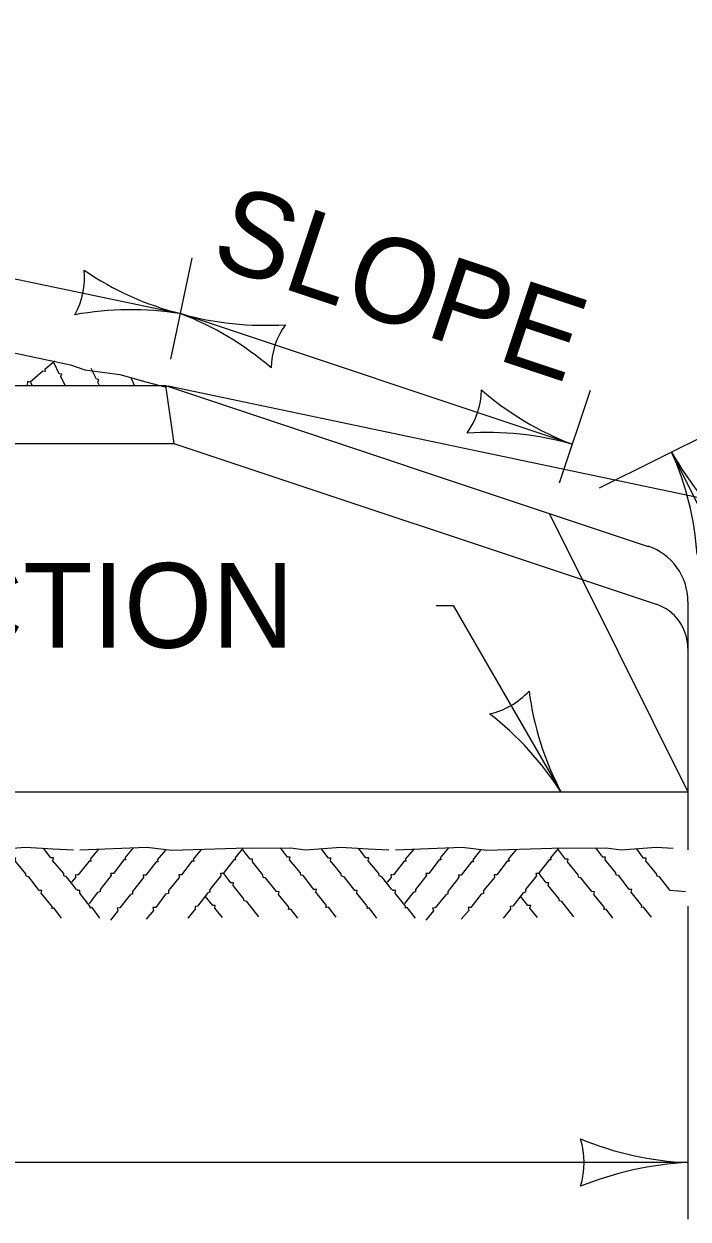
# Model space of a CAD drawing. Extents: x 49991.4 to 50022.1, y 49985 to 50011.4.
# Drawn here: x 50014.7 to 50015.17, y 49996.952 to 49997.798 of the extents above; entities that cross this region are included whole.
import ezdxf

# ---------------------------------------------------------------- set-up
doc = ezdxf.new("R2010")
doc.units = 0
for name, color, linetype in [('Level 1', 7, 'Continuous'), ('Level 2', 7, 'Continuous'), ('Level 3', 7, 'Continuous'), ('Level 4', 7, 'Continuous')]:
    doc.layers.add(name, color=color, linetype=linetype)

msp = doc.modelspace()

# ---------------------------------------------------------------- linework, layer by layer
at = {"layer": 'Level 1'}
for p, q in [((50012.6493, 49997.5423), (50014.7997, 49997.5423)), ((50014.7997, 49997.5423), (50015.1415, 49997.4284)), ((50015.1696, 49997.3894), (50015.1696, 49997.2136))]:
    msp.add_line(p, q, dxfattribs=at)
for points in [[(50014.5862, 49997.5861), (50014.6327, 49997.5783), (50014.6498, 49997.5726), (50014.6948, 49997.5648), (50014.7326, 49997.557), (50014.7427, 49997.5534), (50014.7674, 49997.5501), (50014.786, 49997.5449), (50014.8003, 49997.5411)], [(50014.7215, 49997.5594), (50014.7143, 49997.5536), (50014.7146, 49997.5521), (50014.7131, 49997.5524), (50014.704, 49997.5446), (50014.7022, 49997.545), (50014.7019, 49997.5423)], [(50014.7289, 49997.5423), (50014.7257, 49997.5486), (50014.7264, 49997.5503), (50014.7246, 49997.5506), (50014.721, 49997.5581)], [(50014.7532, 49997.5423), (50014.752, 49997.5446), (50014.7527, 49997.5464), (50014.7509, 49997.5467), (50014.7473, 49997.5542)], [(50014.7779, 49997.5423), (50014.7755, 49997.5476)], [(50014.7054, 49997.5423), (50014.7044, 49997.5444)], [(50014.5163, 49997.2135), (50014.5634, 49997.2154), (50014.5813, 49997.2133), (50014.6267, 49997.2148), (50014.6653, 49997.2151), (50014.6759, 49997.2136), (50014.7008, 49997.2154), (50014.7201, 49997.2142), (50014.7347, 49997.2135)], [(50014.7263, 49997.1651), (50014.7207, 49997.1725), (50014.7193, 49997.1721), (50014.7195, 49997.1734), (50014.7119, 49997.183), (50014.7123, 49997.1847), (50014.7105, 49997.1849), (50014.7031, 49997.1945), (50014.7013, 49997.195), (50014.7009, 49997.1967), (50014.6935, 49997.2059), (50014.6939, 49997.2076), (50014.6919, 49997.2076), (50014.6867, 49997.2145)], [(50014.7368, 49997.1855), (50014.7297, 49997.1945), (50014.7279, 49997.1951), (50014.7278, 49997.1968), (50014.7201, 49997.2059), (50014.7205, 49997.2079), (50014.7187, 49997.2079), (50014.7134, 49997.2148)], [(50014.7524, 49997.2141), (50014.7464, 49997.207), (50014.7471, 49997.2055), (50014.7457, 49997.2055), (50014.7381, 49997.1959), (50014.7373, 49997.1959)], [(50014.7393, 49997.2135), (50014.7865, 49997.2154), (50014.8043, 49997.2133), (50014.8499, 49997.2148), (50014.8883, 49997.2151), (50014.8989, 49997.2136), (50014.9239, 49997.2154), (50014.9432, 49997.2142), (50014.9579, 49997.2135)], [(50014.7769, 49997.2149), (50014.7711, 49997.2079), (50014.7717, 49997.2065), (50014.7704, 49997.2065), (50014.7629, 49997.1969), (50014.7609, 49997.1969), (50014.7613, 49997.1953), (50014.7535, 49997.1855), (50014.7535, 49997.1839), (50014.7518, 49997.1833), (50014.7458, 49997.1755)], [(50014.7997, 49997.2133), (50014.7939, 49997.2065), (50014.7947, 49997.2052), (50014.7932, 49997.2052), (50014.7859, 49997.1956), (50014.7841, 49997.1956), (50014.7842, 49997.1939), (50014.7765, 49997.1842), (50014.7765, 49997.1825), (50014.7749, 49997.1818), (50014.7675, 49997.1725), (50014.7657, 49997.1722), (50014.7661, 49997.1705), (50014.7608, 49997.1639)], [(50014.8253, 49997.2141), (50014.8193, 49997.207), (50014.8201, 49997.2055), (50014.8185, 49997.2055), (50014.8111, 49997.1959), (50014.8093, 49997.1959), (50014.8094, 49997.1941), (50014.8019, 49997.1847), (50014.8019, 49997.1827), (50014.7999, 49997.1821), (50014.7929, 49997.1727), (50014.7909, 49997.1727), (50014.7914, 49997.1707), (50014.7861, 49997.1644)], [(50014.8547, 49997.2149), (50014.8489, 49997.2076), (50014.8497, 49997.2064), (50014.8483, 49997.2064), (50014.8407, 49997.1968), (50014.8388, 49997.1968), (50014.8389, 49997.1951), (50014.8313, 49997.1855), (50014.8313, 49997.1836), (50014.8298, 49997.1831), (50014.8225, 49997.1737), (50014.8207, 49997.1735), (50014.8209, 49997.1716), (50014.8157, 49997.1653)], [(50014.8934, 49997.1653), (50014.8885, 49997.1716), (50014.8869, 49997.1713), (50014.8873, 49997.1727), (50014.8797, 49997.1819), (50014.8802, 49997.1839), (50014.8784, 49997.1841), (50014.8707, 49997.1937), (50014.8689, 49997.1941), (50014.8688, 49997.1959), (50014.8613, 49997.2051), (50014.8615, 49997.207), (50014.8597, 49997.207), (50014.8545, 49997.2135)], [(50014.9205, 49997.1659), (50014.9151, 49997.1731), (50014.9133, 49997.1728), (50014.9138, 49997.1741), (50014.9063, 49997.1835), (50014.9067, 49997.1854), (50014.9048, 49997.1855), (50014.8973, 49997.1953), (50014.8957, 49997.1956), (50014.8953, 49997.1974), (50014.8877, 49997.2065), (50014.8881, 49997.2085), (50014.8862, 49997.2085), (50014.8813, 49997.2149)], [(50014.9493, 49997.1651), (50014.9439, 49997.1725), (50014.9425, 49997.1721), (50014.9427, 49997.1734), (50014.9353, 49997.183), (50014.9355, 49997.1847), (50014.9339, 49997.1849), (50014.9263, 49997.1945), (50014.9245, 49997.195), (50014.9241, 49997.1967), (50014.9167, 49997.2059), (50014.9169, 49997.2076), (50014.9151, 49997.2076), (50014.9101, 49997.2145)], [(50014.9599, 49997.1855), (50014.9529, 49997.1945), (50014.9511, 49997.1951), (50014.9509, 49997.1968), (50014.9433, 49997.2059), (50014.9437, 49997.2079), (50014.9417, 49997.2079), (50014.9365, 49997.2148)], [(50014.9755, 49997.2141), (50014.9695, 49997.207), (50014.9702, 49997.2055), (50014.9687, 49997.2055), (50014.9613, 49997.1959), (50014.9605, 49997.1959)], [(50014.9625, 49997.2135), (50015.0098, 49997.2154), (50015.0273, 49997.2133), (50015.0733, 49997.2148), (50015.1117, 49997.2151), (50015.1223, 49997.2136), (50015.1472, 49997.2154), (50015.1591, 49997.2147)], [(50015.0002, 49997.2149), (50014.9942, 49997.2079), (50014.9949, 49997.2065), (50014.9935, 49997.2065), (50014.9863, 49997.1969), (50014.9841, 49997.1969), (50014.9845, 49997.1953), (50014.9768, 49997.1855), (50014.9768, 49997.1839), (50014.9751, 49997.1833), (50014.9689, 49997.1755)], [(50015.0227, 49997.2133), (50015.0173, 49997.2065), (50015.0179, 49997.2052), (50015.0165, 49997.2052), (50015.0091, 49997.1956), (50015.0073, 49997.1956), (50015.0074, 49997.1939), (50014.9997, 49997.1842), (50014.9997, 49997.1825), (50014.9983, 49997.1818), (50014.9907, 49997.1725), (50014.9889, 49997.1722), (50014.9894, 49997.1705), (50014.9841, 49997.1639)], [(50015.0483, 49997.2141), (50015.0423, 49997.207), (50015.0433, 49997.2055), (50015.0417, 49997.2055), (50015.0344, 49997.1959), (50015.0325, 49997.1959), (50015.0327, 49997.1941), (50015.0249, 49997.1847), (50015.0249, 49997.1827), (50015.0233, 49997.1821), (50015.0159, 49997.1727), (50015.0141, 49997.1727), (50015.0145, 49997.1707), (50015.0092, 49997.1644)], [(50015.0781, 49997.2149), (50015.0721, 49997.2076), (50015.0728, 49997.2064), (50015.0713, 49997.2064), (50015.0639, 49997.1968), (50015.0619, 49997.1968), (50015.0623, 49997.1951), (50015.0547, 49997.1855), (50015.0547, 49997.1836), (50015.0529, 49997.1831), (50015.0457, 49997.1737), (50015.0437, 49997.1735), (50015.0441, 49997.1716), (50015.0389, 49997.1653)], [(50015.1165, 49997.1653), (50015.1118, 49997.1716), (50015.1101, 49997.1713), (50015.1105, 49997.1727), (50015.1029, 49997.1819), (50015.1034, 49997.1839), (50015.1015, 49997.1841), (50015.0939, 49997.1937), (50015.0923, 49997.1941), (50015.0919, 49997.1959), (50015.0843, 49997.2051), (50015.0848, 49997.207), (50015.0829, 49997.207), (50015.0779, 49997.2135)], [(50015.1439, 49997.1659), (50015.1382, 49997.1731), (50015.1367, 49997.1728), (50015.1369, 49997.1741), (50015.1293, 49997.1835), (50015.1299, 49997.1854), (50015.1281, 49997.1855), (50015.1207, 49997.1953), (50015.1187, 49997.1956), (50015.1185, 49997.1974), (50015.1111, 49997.2065), (50015.1112, 49997.2085), (50015.1094, 49997.2085), (50015.1043, 49997.2149)], [(50015.1679, 49997.1838), (50015.1569, 49997.1849), (50015.1495, 49997.1945), (50015.1477, 49997.195), (50015.1473, 49997.1967), (50015.1399, 49997.2059), (50015.1401, 49997.2076), (50015.1382, 49997.2076), (50015.1333, 49997.2145)], [(50014.7369, 49997.1959), (50014.7361, 49997.1959), (50014.7362, 49997.1941), (50014.7333, 49997.1907)], [(50014.8658, 49997.1661), (50014.8573, 49997.1771), (50014.8555, 49997.1775), (50014.8551, 49997.1791), (50014.8477, 49997.1884), (50014.8479, 49997.1902), (50014.8461, 49997.1902), (50014.8411, 49997.1968)], [(50014.9601, 49997.1959), (50014.9594, 49997.1959), (50014.9595, 49997.1941), (50014.9567, 49997.1907)], [(50015.0889, 49997.1661), (50015.0803, 49997.1771), (50015.0787, 49997.1775), (50015.0783, 49997.1791), (50015.0707, 49997.1884), (50015.0711, 49997.1902), (50015.0692, 49997.1902), (50015.0643, 49997.1968)], [(50014.7533, 49997.1653), (50014.7479, 49997.1727), (50014.7464, 49997.1722), (50014.7465, 49997.1735), (50014.7391, 49997.183), (50014.7393, 49997.1848), (50014.7377, 49997.1849), (50014.7373, 49997.1855)], [(50014.9767, 49997.1653), (50014.9709, 49997.1727), (50014.9695, 49997.1722), (50014.9699, 49997.1735), (50014.9624, 49997.183), (50014.9627, 49997.1848), (50014.9609, 49997.1849), (50014.9605, 49997.1855)], [(50014.8401, 49997.1656), (50014.8347, 49997.1722), (50014.8349, 49997.1741), (50014.8333, 49997.1741), (50014.8279, 49997.1809)], [(50015.0632, 49997.1656), (50015.0578, 49997.1722), (50015.0583, 49997.1741), (50015.0563, 49997.1741), (50015.0511, 49997.1809)]]:
    msp.add_lwpolyline(points, dxfattribs=at)
msp.add_arc((50015.12844, 49997.38946), 0.0411, 0, 71.54164, dxfattribs=at)
at = {"layer": 'Level 3'}
for p, q in [((50013.83176, 49997.79821), (50014.8104, 49997.59312)), ((50014.8036, 49997.5609), (50014.8187, 49997.6324)), ((50015.08764, 49997.50072), (50014.8104, 49997.59312)), ((50015.1003, 49997.5387), (50015.0784, 49997.47301)), ((50015.10705, 49997.46975), (50015.1939, 49997.513)), ((50015.15803, 49997.49514), (50015.25619, 49997.29792)), ((50014.99145, 49997.3866), (50015.0034, 49997.3866)), ((50015.0034, 49997.3866), (50015.0797, 49997.2547)), ((50015.1696, 49997.1736), (50015.1696, 49996.9522)), ((50015.1696, 49996.9922), (50014.41502, 49996.9922))]:
    msp.add_line(p, q, dxfattribs=at)
for centre, radius, start, end in [((50014.68994, 49997.61837), 0.05258, 330.30225, 6.02461), ((50014.86275, 49997.80003), 0.21343, 235.61944, 255.80295), ((50014.77538, 49997.3722), 0.22368, 80.99074, 100.24059), ((50014.73459, 49997.39361), 0.21343, 49.00916, 69.19266), ((50014.87063, 49997.80854), 0.22368, 254.38046, 273.63031), ((50014.92717, 49997.55417), 0.05258, 143.69196, 179.41433), ((50014.97088, 49997.53967), 0.05258, 323.69196, 359.41433), ((50015.16346, 49997.70023), 0.21343, 229.00916, 249.19266), ((50015.02742, 49997.2853), 0.22368, 74.38046, 93.63031), ((50014.96321, 49997.40797), 0.21343, 3.92051, 24.10401), ((50015.35311, 49997.60457), 0.22368, 209.29181, 228.54166), ((50015.0181, 49997.36126), 0.05258, 282.17009, 317.89245), ((50015.26872, 49997.35381), 0.21343, 187.48728, 207.67079), ((50014.89181, 49997.13334), 0.22368, 32.85858, 52.10843), ((50015.17876, 49997.21433), 0.22232, 247.45601, 267.63952), ((50015.04139, 49996.9922), 0.05477, 342.13882, 17.86118), ((50015.18109, 49996.75949), 0.233, 92.82731, 112.07716)]:
    msp.add_arc(centre, radius, start, end, dxfattribs=at)
at = {"layer": 'Level 4'}
for p, q in [((50014.7997, 49997.5423), (50014.8057, 49997.5013)), ((50014.8017, 49997.542), (50016.1675, 49997.2547)), ((50012.6493, 49997.5013), (50014.8057, 49997.5013)), ((50014.8057, 49997.5013), (50015.147, 49997.3875)), ((50015.0713, 49997.4518), (50015.1696, 49997.2547)), ((50012.6493, 49997.2547), (50015.1696, 49997.2547))]:
    msp.add_line(p, q, dxfattribs=at)
msp.add_arc((50015.13666, 49997.3563), 0.03288, 0, 71.57491, dxfattribs=at)

# ---------------------------------------------------------------- texts
at = {"layer": 'Level 2'}
msp.add_text('SLOPE', height=0.06, rotation=341.57524, dxfattribs=at).set_placement((50014.82997, 49997.62874))
msp.add_text('END SECTION', height=0.06, dxfattribs=at).set_placement((50014.34248, 49997.3566))

doc.saveas('drawing.dxf')
